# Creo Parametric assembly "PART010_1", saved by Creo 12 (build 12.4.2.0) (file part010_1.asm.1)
Units: Custom; MM, KILOGRAM, SECS

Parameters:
  PTC_WM_ITERATION = "0"
  PTC_WM_VERSION = "-.0"
  PTC_WM_LIFECYCLE_STATE = "In Work"
  PTC_WM_LIFECYCLE = "MO_CADDocument"
  PTC_WM_CREATED_BY = "Maximilian Roepper (Z0017RMS: MO)"
  PTC_WM_CREATED_ON = "18-Sep-26 11:36:42 AM"
  PTC_WM_MODIFIED_BY = "Maximilian Roepper (Z0017RMS: MO)"
  PTC_WM_MODIFIED_ON = "18-Sep-26 11:36:46 AM"
  PDMLINKNUMBER = "PDM000071455274"
  PTC_WM_NUMBER = "PDM000071455274"

Other parameters: WEIGHT, WEIGHT_FACTOR, WEIGHT_ADD, MC_ERRORS, SUPPLIER

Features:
  1. coordinate system
  2. imported feature
  3. component "SHAPESTRING256_1"

Other named items: DRW_VIEW_ORG, ROUGH-GROB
